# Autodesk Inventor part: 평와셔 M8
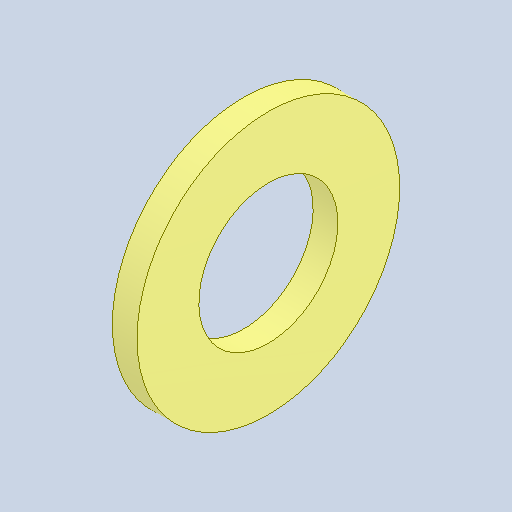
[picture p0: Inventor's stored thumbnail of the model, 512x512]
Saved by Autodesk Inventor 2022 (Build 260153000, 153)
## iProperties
Created: 2024-11
Part Number: 평와셔 M8
Material: 강철, 연강
Description: 평면 와셔
Document SubType Name: Modeling
Designer: PC-12
Density: 7.85 g/cm^3
Appearance: 기본값
Author: jhkim
Sending System: Autodesk Inventor 2025
Preprocessor: ST-DEVELOPER v20
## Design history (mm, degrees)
node "평와셔 M81"
node "솔리드1"
body "Solid1"
